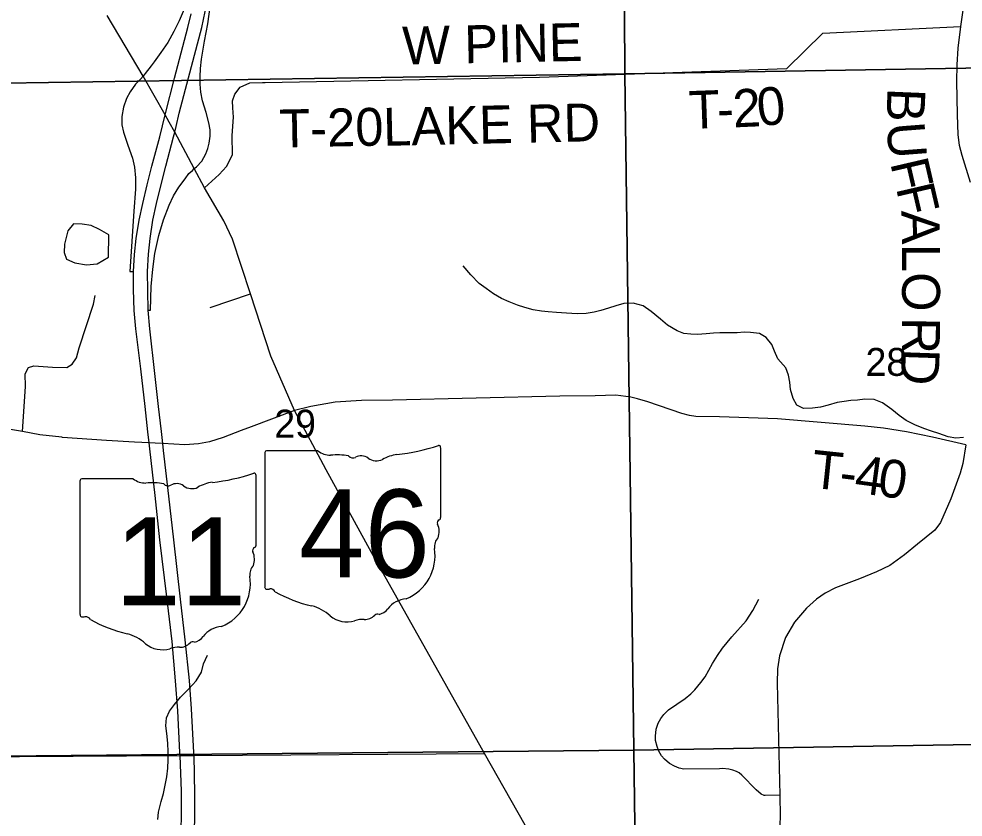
# Model space of a CAD drawing. Extents: x 0 to 36.9, y 0 to 22.
# Drawn here: x 5.318 to 6.733, y 15.386 to 16.582 of the extents above; entities that cross this region are included whole.
import ezdxf

# ---------------------------------------------------------------- set-up
doc = ezdxf.new("R2010")
doc.units = 0
for name, color, linetype in [('GM_X_County_Road', 7, 'Continuous'), ('GM_X_County_Road_Text', 7, 'Continuous'), ('GM_X_Interchange_Ramps', 7, 'Continuous'), ('GM_X_Minor_Lake', 7, 'Continuous'), ('GM_X_Minor_River', 7, 'Continuous'), ('GM_X_Section', 7, 'Continuous'), ('GM_X_Section_Text', 7, 'Continuous'), ('GM_X_State_Location', 7, 'Continuous'), ('GM_X_State_Route', 7, 'Continuous'), ('GM_X_State_Shield', 7, 'Continuous'), ('GM_X_Township_Road', 7, 'Continuous'), ('GM_X_Township_Road_Text', 7, 'Continuous')]:
    doc.layers.add(name, color=color, linetype=linetype)

msp = doc.modelspace()

# ---------------------------------------------------------------- linework, layer by layer
at = {"layer": 'GM_X_County_Road'}
msp.add_line((5.7307, 15.9951), (5.6659, 15.9707), dxfattribs=at)
for points in [[(6.7379, 16.634), (6.7285, 16.5707), (6.7248, 16.5378), (6.723, 16.5133), (6.7225, 16.488), (6.7236, 16.4384), (6.7248, 16.4082), (6.7268, 16.3929), (6.7306, 16.3779), (6.7433, 16.3374)], [(5.3825, 15.9549), (5.3493, 15.9585), (5.3236, 15.9637), (5.2563, 15.9747), (5.2373, 15.9775), (5.2243, 15.9786), (5.2175, 15.9787)], [(5.6659, 15.9707), (5.6511, 15.9651), (5.6241, 15.9548), (5.6033, 15.9479), (5.5871, 15.9452), (5.5667, 15.9438), (5.5337, 15.9455), (5.5223, 15.946), (5.5131, 15.9465), (5.4911, 15.9474), (5.4491, 15.9501), (5.3834, 15.9548), (5.3825, 15.9549)], [(6.7367, 15.9435), (6.7324, 15.9156), (6.728, 15.9013), (6.7142, 15.8628), (6.6988, 15.8271), (6.6903, 15.8157), (6.6644, 15.7947), (6.645, 15.779), (6.623, 15.7629), (6.603, 15.7532), (6.5772, 15.7429), (6.5416, 15.7295), (6.5261, 15.7215), (6.513, 15.7122), (6.4979, 15.6991), (6.4798, 15.6781), (6.4667, 15.6551), (6.4575, 15.6275), (6.4547, 15.6082), (6.4538, 15.5867), (6.4578, 15.4187), (6.4585, 15.3868), (6.4576, 15.363)], [(4.2587, 15.4652), (4.4807, 15.4671), (5.2386, 15.4759), (5.5595, 15.4781), (5.5699, 15.4782), (5.5803, 15.4783), (6.0155, 15.4812)]]:
    msp.add_lwpolyline(points, dxfattribs=at)
at = {"layer": 'GM_X_Interchange_Ramps'}
for points in [[(5.5806, 16.6115), (5.5732, 16.614), (5.5656, 16.5967), (5.5579, 16.5791), (5.5503, 16.5629), (5.5411, 16.5466), (5.5308, 16.5317), (5.5207, 16.5178), (5.516, 16.5115), (5.5071, 16.5), (5.504, 16.4959)], [(5.5806, 16.3575), (5.584, 16.3603), (5.592, 16.3688), (5.5978, 16.3798), (5.6009, 16.3877), (5.6029, 16.3957), (5.6043, 16.4061), (5.6043, 16.4157), (5.6025, 16.4264), (5.5984, 16.4417), (5.5932, 16.4593), (5.5906, 16.4722), (5.5895, 16.4843), (5.5893, 16.4953), (5.5899, 16.5078), (5.5915, 16.5216), (5.596, 16.5483), (5.6011, 16.5745), (5.605, 16.6036), (5.5996, 16.605)], [(5.504, 16.4959), (5.5002, 16.4917), (5.4927, 16.4839), (5.4845, 16.4728), (5.4792, 16.4628), (5.4747, 16.4497), (5.4723, 16.4356), (5.4724, 16.4231), (5.4745, 16.4122), (5.4814, 16.3926), (5.4883, 16.3732), (5.491, 16.3595), (5.4926, 16.3435), (5.4929, 16.3266), (5.4903, 16.2938), (5.4844, 16.2035), (5.4897, 16.2034)], [(5.5117, 16.1452), (5.5153, 16.1455), (5.5162, 16.1807), (5.5187, 16.207), (5.5216, 16.2303), (5.5275, 16.2572), (5.5346, 16.2807), (5.5431, 16.303), (5.5494, 16.3169), (5.5574, 16.3298), (5.5669, 16.3424), (5.5727, 16.35), (5.5778, 16.3549), (5.5806, 16.3575)]]:
    msp.add_lwpolyline(points, dxfattribs=at)
at = {"layer": 'GM_X_Minor_Lake'}
for points in [[(5.4528, 16.2585), (5.4386, 16.2662), (5.4264, 16.2725), (5.4126, 16.2745), (5.3997, 16.2747), (5.3915, 16.2643), (5.3861, 16.2445), (5.386, 16.2319), (5.3895, 16.2221), (5.4018, 16.2166), (5.4193, 16.2135), (5.4353, 16.2149), (5.4522, 16.2247)], [(5.4522, 16.2247), (5.4528, 16.2585)]]:
    msp.add_lwpolyline(points, dxfattribs=at)
at = {"layer": 'GM_X_Minor_River'}
for points in [[(6.733, 15.9546), (6.7216, 15.9536), (6.7102, 15.9557), (6.6964, 15.9607), (6.685, 15.9643), (6.6735, 15.9683), (6.6601, 15.9734), (6.6471, 15.9803), (6.6367, 15.9877), (6.6259, 15.9967), (6.6117, 16.0067), (6.5991, 16.0114), (6.5854, 16.0123), (6.5744, 16.0105), (6.5642, 16.01), (6.5543, 16.0087), (6.5437, 16.007), (6.5305, 16.0029), (6.5188, 16.0001), (6.507, 15.9987), (6.4937, 15.9981), (6.4834, 16.0032), (6.4779, 16.013), (6.4742, 16.0266), (6.4729, 16.0376), (6.4708, 16.0482), (6.4672, 16.0591), (6.4552, 16.0726), (6.4501, 16.0839), (6.4461, 16.094), (6.4375, 16.1045), (6.4276, 16.1104), (6.4142, 16.1121), (6.4047, 16.1123), (6.3941, 16.1117), (6.3842, 16.1115), (6.3683, 16.1116), (6.3588, 16.1111), (6.3478, 16.1101), (6.3345, 16.1091), (6.3247, 16.1093), (6.314, 16.1103), (6.3041, 16.1143), (6.2899, 16.1231), (6.2791, 16.132), (6.2652, 16.1436), (6.2533, 16.1517), (6.2384, 16.156), (6.2244, 16.1554), (6.2123, 16.1517), (6.2013, 16.1485), (6.1896, 16.1449), (6.1798, 16.1424), (6.1677, 16.1403), (6.1544, 16.1401), (6.1384, 16.1409), (6.1236, 16.1418), (6.1107, 16.1427), (6.1008, 16.144), (6.0882, 16.1461), (6.076, 16.1493), (6.0649, 16.1529), (6.0523, 16.158), (6.0408, 16.1631), (6.0289, 16.1701), (6.0178, 16.1779), (6.0074, 16.1853), (5.995, 16.1983), (5.9838, 16.2118)], [(5.526, 15.3821), (5.527, 15.3931), (5.5313, 15.4091), (5.5345, 15.421), (5.5373, 15.4335), (5.5394, 15.4461), (5.5411, 15.459), (5.5416, 15.4716), (5.5418, 15.4834), (5.5412, 15.4966), (5.5395, 15.511), (5.5382, 15.5228), (5.5391, 15.5346), (5.5435, 15.5445), (5.5513, 15.5545), (5.5599, 15.5653), (5.5726, 15.578), (5.5835, 15.59), (5.5916, 15.603), (5.5944, 15.6156), (5.6007, 15.6286)]]:
    msp.add_lwpolyline(points, dxfattribs=at)
at = {"layer": 'GM_X_Section'}
for points in [[(7.1983, 17.5272), (7.2171, 16.5161), (6.226, 16.4996), (6.2201, 17.5106)], [(6.2201, 17.5106), (6.226, 16.4996), (5.2292, 16.4845), (5.2141, 17.498)], [(6.226, 16.4996), (7.2171, 16.5161), (7.2257, 15.5025), (6.2395, 15.4861)], [(5.2292, 16.4845), (6.226, 16.4996), (6.2395, 15.4861), (5.2381, 15.4765)], [(6.2395, 15.4861), (7.2257, 15.5025), (7.2369, 14.4927), (6.2525, 14.4815)], [(5.2381, 15.4765), (6.2395, 15.4861), (6.2525, 14.4815), (5.2461, 14.474)]]:
    msp.add_lwpolyline(points, close=True, dxfattribs=at)
at = {"layer": 'GM_X_State_Route'}
for points in [[(5.5535, 16.4209), (5.5583, 16.4405), (5.5721, 16.4934), (5.5919, 16.5691), (5.5996, 16.605)], [(6.3231, 15.051), (6.2562, 15.1039), (6.2353, 15.1223), (6.2258, 15.1314), (6.2075, 15.1513), (6.1924, 15.1718), (6.1795, 15.1927), (6.1563, 15.2327), (6.0155, 15.4812), (5.8461, 15.7824), (5.7784, 15.9063), (5.7307, 15.9951), (5.6955, 16.0767), (5.6648, 16.1701), (5.6378, 16.2518), (5.6249, 16.2792), (5.5961, 16.329), (5.5806, 16.3575), (5.5514, 16.4121), (5.5432, 16.4273), (5.5369, 16.4383), (5.504, 16.4959), (5.45, 16.5871)], [(5.5609, 15.3306), (5.5616, 15.4247), (5.5595, 15.4781), (5.5593, 15.4824), (5.5563, 15.5451), (5.5525, 15.5901), (5.5474, 15.6489), (5.5397, 15.7157), (5.5293, 15.8012), (5.5223, 15.8678), (5.5142, 15.9376), (5.5131, 15.9465), (5.5109, 15.9632), (5.5071, 16.0012), (5.5007, 16.0573), (5.4933, 16.1174), (5.4908, 16.1449), (5.4895, 16.1766), (5.4897, 16.2034), (5.491, 16.2291), (5.4935, 16.2527), (5.4979, 16.2802), (5.5034, 16.3052), (5.5101, 16.3333), (5.517, 16.361), (5.5289, 16.4052), (5.5369, 16.4383), (5.5374, 16.4403), (5.5512, 16.4932), (5.571, 16.5689), (5.5759, 16.5897)], [(5.581, 15.3314), (5.5815, 15.4206), (5.5803, 15.4783), (5.5802, 15.4826), (5.5764, 15.5483), (5.5734, 15.5904), (5.5669, 15.6514), (5.5601, 15.7124), (5.5502, 15.8014), (5.5425, 15.8667), (5.5348, 15.935), (5.5337, 15.9455), (5.5318, 15.9634), (5.5272, 16.0013), (5.5215, 16.0505), (5.5142, 16.1176), (5.5117, 16.1452), (5.5106, 16.2036), (5.5119, 16.2293), (5.5144, 16.253), (5.5188, 16.2804), (5.5242, 16.3054), (5.531, 16.3336), (5.5379, 16.3612), (5.5497, 16.4054), (5.5514, 16.4121), (5.5535, 16.4209)]]:
    msp.add_lwpolyline(points, dxfattribs=at)
at = {"layer": 'GM_X_State_Shield'}
for p, q in [((5.6862, 15.931), (5.6862, 15.7309)), ((5.766, 15.9345), (5.6888, 15.9345)), ((5.9499, 15.8347), (5.9499, 15.9394)), ((5.4095, 15.8894), (5.4095, 15.6892)), ((5.4893, 15.8928), (5.4121, 15.8928)), ((5.6732, 15.7931), (5.6732, 15.8978)), ((5.9498, 15.8348), (5.9499, 15.8347)), ((5.6732, 15.7931), (5.6732, 15.7931))]:
    msp.add_line(p, q, dxfattribs=at)
for centre, radius, start, end in [((5.6892, 15.9314), 0.00305, 98.1301, 188.1301), ((5.7844, 15.9577), 0.0296, 231.6195, 271.1119), ((5.8916, 15.8733), 0.0563, 97.3462, 120.7689), ((5.8559, 16.2073), 0.2796, 275.8445, 288.9065), ((5.9469, 15.9399), 0.00294, 351.8621, 97.738), ((5.7942, 15.8221), 0.1064, 80.4867, 94.9883), ((5.8184, 15.9325), 0.00855, 219.7921, 297.1024), ((5.8309, 15.9094), 0.0178, 54.4667, 119.1411), ((5.8538, 15.9411), 0.0214, 233.8562, 294.8282), ((5.5793, 16.1656), 0.2796, 275.8445, 288.9065), ((5.6703, 15.8982), 0.00294, 351.8621, 97.738), ((5.4125, 15.8898), 0.00305, 98.1301, 188.1301), ((5.5077, 15.916), 0.0296, 231.6195, 271.1119), ((5.5176, 15.7804), 0.1064, 80.4867, 94.9883), ((5.6149, 15.8317), 0.0563, 97.3462, 120.7689), ((5.5417, 15.8908), 0.00855, 219.7921, 297.1024), ((5.5542, 15.8677), 0.0178, 54.4667, 119.1411), ((5.5772, 15.8994), 0.0214, 233.8562, 294.8282), ((5.9492, 15.8271), 0.00454, 107.944, 210.337), ((5.9467, 15.8343), 0.00314, 289.6038, 7.7341), ((5.9203, 15.8138), 0.0273, 340.033, 23.6496), ((5.9604, 15.7909), 0.0198, 136.8065, 186.9296), ((5.6725, 15.7854), 0.00454, 107.944, 210.337), ((5.6701, 15.7927), 0.00314, 289.6038, 7.7341), ((5.8716, 15.7776), 0.0699, 292.3089, 8.9858), ((5.6436, 15.7722), 0.0273, 340.033, 23.6496), ((5.6837, 15.7493), 0.0198, 136.8065, 186.9296), ((5.5949, 15.7359), 0.0699, 292.3089, 8.9858), ((5.6892, 15.7305), 0.00308, 171.9584, 258.3066), ((5.6897, 15.7509), 0.0235, 267.339, 280.6039), ((5.6945, 15.7194), 0.00848, 29.7484, 93.2717), ((5.8016, 15.8992), 0.2019, 240.4129, 257.1985), ((5.9011, 15.6747), 0.0383, 94.4031, 142.5768), ((5.4126, 15.6888), 0.00308, 171.9584, 258.3066), ((5.7414, 15.641), 0.0632, 47.1842, 75.836), ((5.8551, 15.684), 0.00601, 65.7517, 132.6484), ((5.8526, 15.7115), 0.0226, 282.8732, 323.2771), ((5.413, 15.7093), 0.0235, 267.339, 280.6039), ((5.4179, 15.6777), 0.00848, 29.7484, 93.2717), ((5.5249, 15.8575), 0.2019, 240.4129, 257.1985), ((5.8097, 15.7184), 0.0401, 230.7004, 286.2918), ((5.8329, 15.6492), 0.0329, 85.6951, 111.2099), ((5.8358, 15.7034), 0.0214, 268.777, 315.5493), ((5.4647, 15.5993), 0.0632, 47.1842, 75.836), ((5.6244, 15.6331), 0.0383, 94.4031, 142.5768), ((5.5591, 15.6617), 0.0214, 268.777, 315.5493), ((5.5785, 15.6423), 0.00601, 65.7517, 132.6484), ((5.5759, 15.6698), 0.0226, 282.8732, 323.2771), ((5.533, 15.6767), 0.0401, 230.7004, 286.2918), ((5.5562, 15.6075), 0.0329, 85.6951, 111.2099)]:
    msp.add_arc(centre, radius, start, end, dxfattribs=at)
at = {"layer": 'GM_X_Township_Road'}
msp.add_line((5.6044, 16.1492), (5.6648, 16.1701), dxfattribs=at)
for points in [[(5.6869, 16.4868), (6.0981, 16.4945), (6.4687, 16.5078), (6.5223, 16.5607), (6.7285, 16.5707)], [(5.5961, 16.329), (5.6178, 16.3486), (5.6291, 16.3605), (5.6378, 16.3781), (5.6374, 16.407), (5.6395, 16.4345), (5.6387, 16.4485), (5.6381, 16.4592), (5.6413, 16.4691), (5.6495, 16.4796), (5.6641, 16.4863), (5.6829, 16.4867), (5.6869, 16.4868)], [(5.3236, 15.9637), (5.3278, 16.0309), (5.3272, 16.0498), (5.3325, 16.0593), (5.3404, 16.0619), (5.3682, 16.0598), (5.3897, 16.0593), (5.3976, 16.0645), (5.4044, 16.074), (5.4081, 16.0892), (5.4296, 16.1544), (5.4323, 16.1675)], [(6.7367, 15.9435), (6.6869, 15.9549), (6.6479, 15.9633), (6.6132, 15.9686), (6.5852, 15.9717), (6.4543, 15.9825), (6.3674, 15.9854), (6.3322, 15.9862), (6.3229, 15.9877), (6.311, 15.9908), (6.2601, 16.0082), (6.245, 16.0126), (6.2347, 16.0153), (6.2272, 16.0163), (6.2122, 16.0179), (6.1815, 16.017), (6.1284, 16.0168), (5.8776, 16.0105), (5.831, 16.0102), (5.792, 16.0074), (5.7555, 16.0009), (5.7307, 15.9951)], [(6.4578, 15.4187), (6.4359, 15.418), (6.4345, 15.418), (6.4299, 15.4201), (6.4223, 15.4268), (6.4012, 15.4487), (6.3972, 15.452), (6.3932, 15.4542), (6.3878, 15.4564), (6.3818, 15.4576), (6.3722, 15.4585), (6.3678, 15.458), (6.3143, 15.4578), (6.3072, 15.4593), (6.3, 15.4622), (6.2925, 15.4663), (6.2851, 15.4727), (6.2806, 15.4778), (6.2767, 15.4845), (6.274, 15.4916), (6.2718, 15.5005), (6.2717, 15.507), (6.2729, 15.5175), (6.2758, 15.5268), (6.2795, 15.5335), (6.284, 15.5398), (6.2913, 15.5464), (6.3161, 15.5636), (6.3246, 15.5703), (6.3305, 15.5767), (6.3397, 15.5874), (6.3462, 15.5961), (6.3571, 15.616), (6.3644, 15.628), (6.372, 15.6389), (6.386, 15.6558), (6.4078, 15.6797), (6.4175, 15.6953), (6.4267, 15.7125)]]:
    msp.add_lwpolyline(points, dxfattribs=at)

# ---------------------------------------------------------------- texts
at = {"layer": 'GM_X_County_Road_Text'}
for s, rotation, p in [('B', 267.595, (6.6196, 16.4793)), ('U', 274.4557, (6.6178, 16.4252)), ('F', 283.0786, (6.6231, 16.3662)), ('F', 283.1363, (6.6318, 16.3288)), ('A', 271.2314, (6.6401, 16.2945)), ('L', 270.0514, (6.6412, 16.2448)), ('O', 270.0073, (6.6412, 16.2024)), ('R', 269.6682, (6.6412, 16.1349)), ('D', 267.9924, (6.6409, 16.0887))]:
    msp.add_text(s, height=0.0568, rotation=rotation, dxfattribs=at).set_placement(p)
at = {"layer": 'GM_X_Section_Text'}
for s, p in [('28', (6.5865, 16.047)), ('29', (5.7007, 15.9545))]:
    msp.add_text(s, height=0.04186, rotation=0, dxfattribs=at).set_placement(p)
at = {"layer": 'GM_X_State_Location'}
for s, p in [('s', (5.8151, 15.8177)), ('r', (5.815, 15.8177)), ('s', (5.5384, 15.776)), ('r', (5.5384, 15.776))]:
    msp.add_text(s, height=0.000189, dxfattribs=at).set_placement(p)
for s, p in [('46', (5.7674, 15.8039)), ('11', (5.4907, 15.7622))]:
    msp.add_text(s, height=0.000189, rotation=0, dxfattribs=at).set_placement(p)
at = {"layer": 'GM_X_State_Shield'}
for s, p in [('46', (5.7377, 15.745)), ('11', (5.4622, 15.7033))]:
    msp.add_text(s, height=0.13184, dxfattribs=at).set_placement(p)
at = {"layer": 'GM_X_Township_Road_Text'}
for s, height, rotation, p in [('W PINE', 0.05682, 1.1947, (5.8929, 16.5134)), ('0', 0.0568, 5.3745, (6.4263, 16.421)), ('T', 0.0568, 2.0521, (6.3225, 16.4169)), ('2', 0.0568, 2.5438, (6.3885, 16.4192)), ('LAKE RD', 0.05682, 1.2787, (5.8642, 16.3916)), ('T-20', 0.05682, 1.061, (5.7084, 16.3892)), ('-', 0.0568, 2.0775, (6.3649, 16.4184)), ('T', 0.0568, 353.9696, (6.5032, 15.8797)), ('4', 0.0568, 352.3141, (6.5682, 15.8724)), ('0', 0.0568, 351.899, (6.6027, 15.8677)), ('-', 0.0568, 352.9534, (6.5452, 15.8752))]:
    msp.add_text(s, height=height, rotation=rotation, dxfattribs=at).set_placement(p)

doc.saveas('drawing.dxf')
